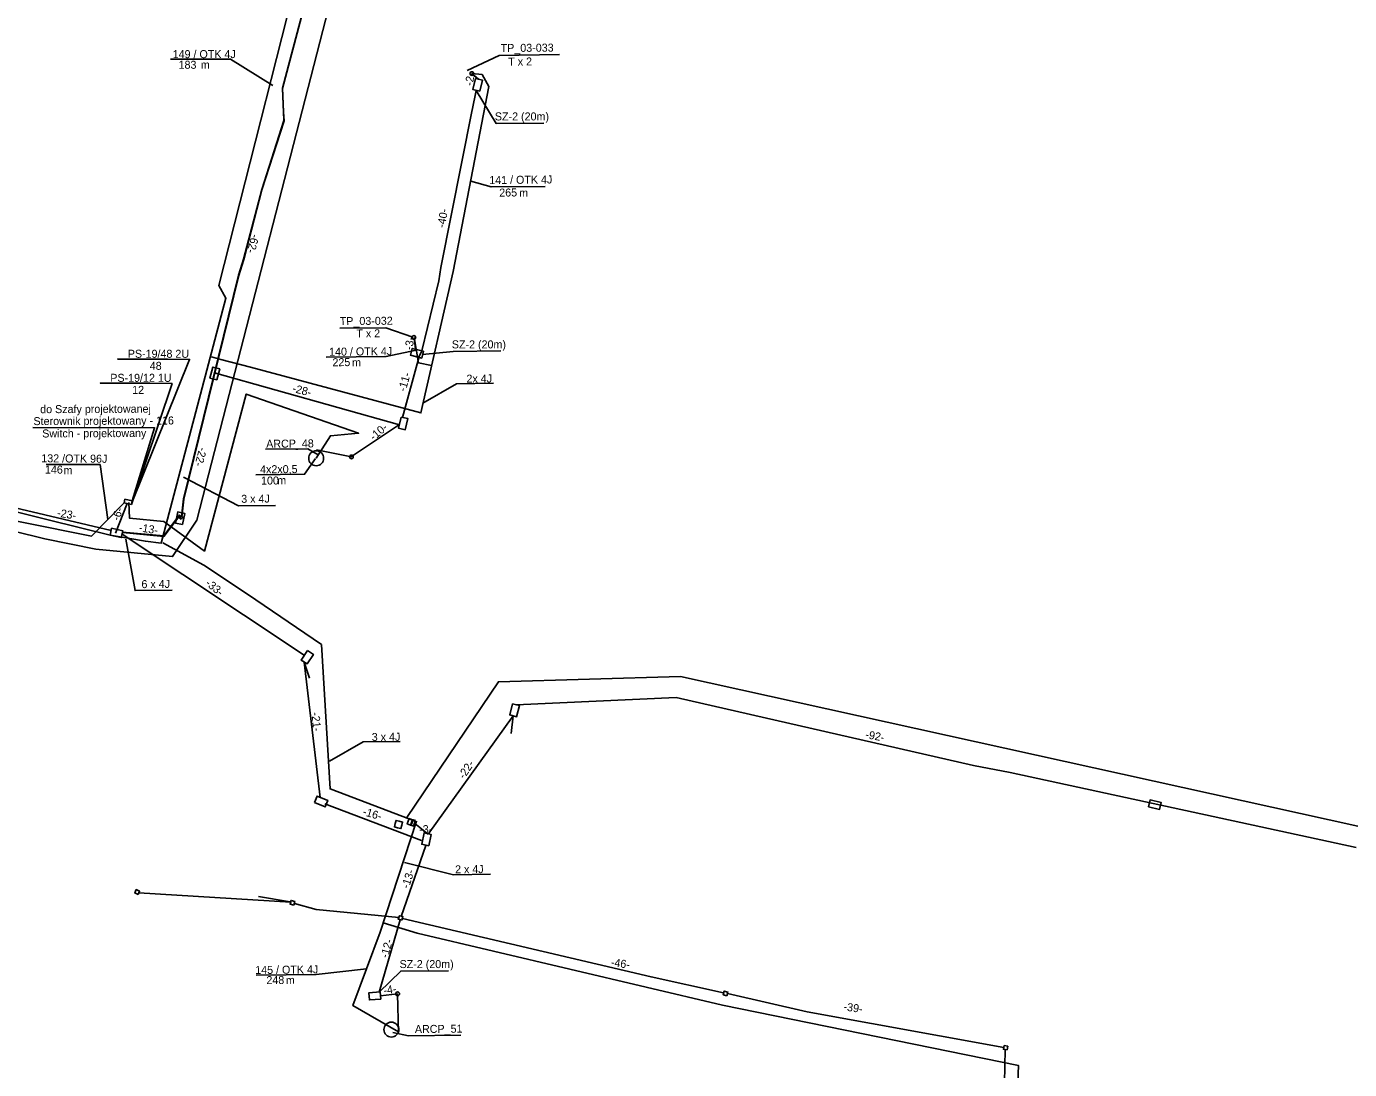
# Model space of a CAD drawing. Extents: x 6494530 to 6506885, y 5884901 to 5892312.
# Drawn here: x 6500530.3 to 6500708, y 5887871.4 to 5888011.5 of the extents above; entities that cross this region are included whole.
import ezdxf

# ---------------------------------------------------------------- set-up
doc = ezdxf.new("R2010")
doc.units = 0
for name, color, linetype in [('kabel do kamery ARCP', 7, 'Continuous'), ('kabel OTK do tab pasaż', 7, 'Continuous'), ('kabel W KANALIZACJI ISTN', 7, 'Continuous'), ('kamery ARCP_nowe', 7, 'Continuous'), ('Kanalizacja_proj', 7, 'Continuous'), ('NOWY OPIS STEROWNIKA', 7, 'Continuous'), ('opis ARCP', 7, 'Continuous'), ('opis kabla CCTV_OTK', 7, 'Continuous'), ('opis kabla infopasażer_OTK', 7, 'Continuous'), ('opis kabla kamery ARCP', 7, 'Continuous'), ('opis kabla otk', 7, 'Continuous'), ('opis PS', 7, 'Continuous'), ('opis SZ-2', 7, 'Continuous'), ('opis tablic inf przystankowej', 7, 'Continuous'), ('proj wysięgnik', 7, 'Continuous'), ('projektowany słup_do_kamery ARCP', 7, 'Continuous'), ('SKR-2', 7, 'Continuous'), ('sterownik', 7, 'Continuous'), ('studnie do wyrysu', 7, 'Continuous'), ('trasa kanalizacji do wyrysu', 7, 'Continuous'), ('Warstwa 59', 7, 'Continuous'), ('Warstwa 62', 7, 'Continuous'), ('WOJEWÓDZKIE', 7, 'Continuous')]:
    doc.layers.add(name, color=color, linetype=linetype)

# ---------------------------------------------------------------- blocks, each defined once
blk = doc.blocks.new('ELARM2_66')
at = {"layer": 'Warstwa 59'}
blk.add_lwpolyline([(0, 0.45), (0.45, 0.45), (0.45, 0), (0.45, -0.45), (0, -0.45), (-0.45, -0.45), (-0.45, 0), (-0.45, 0.45)], close=True, dxfattribs=at)

msp = doc.modelspace()

# ---------------------------------------------------------------- linework, layer by layer
at = {"layer": 'kabel do kamery ARCP'}
msp.add_lwpolyline([(6500569.19, 5887953.51), (6500571.11, 5887956.53), (6500574.89, 5887956.87), (6500559.79, 5887962.13), (6500554.19, 5887941.03), (6500548.73, 5887945.01), (6500544.1, 5887945.46), (6500544.03, 5887947.58)], dxfattribs=at)
at = {"layer": 'kabel OTK do tab pasaż'}
for points in [[(6500576.12, 5888053.57), (6500579.04, 5888052.79), (6500573.17, 5888030.4), (6500568.77, 5888026.66), (6500556.12, 5887976.71), (6500557.07, 5887975.01), (6500548.38, 5887942.11), (6500546.25, 5887942.36), (6500541.51, 5887943.19), (6500533.2, 5887945.22)], [(6500590.1, 5888005.2), (6500591.48, 5888005.06), (6500592.36, 5888003.44), (6500587.61, 5887978.59), (6500583.26, 5887959.61), (6500560.36, 5887965.77), (6500556.37, 5887966.78), (6500555.14, 5887967.14)], [(6500582.33, 5887969.73), (6500582.95, 5887966.35), (6500584.66, 5887965.96)], [(6500461.48, 5887931.47), (6500462.86, 5887930.45), (6500462.92, 5887926.96), (6500481.93, 5887923.99), (6500485.89, 5887929.87), (6500492.78, 5887940.43), (6500500.55, 5887951.93), (6500505.96, 5887955.91), (6500512.86, 5887954.64), (6500524.49, 5887947.38), (6500533.2, 5887945.22)], [(6500548.61, 5887942.15), (6500554.1, 5887939.13), (6500559.98, 5887935.23), (6500569.89, 5887928.48), (6500571.06, 5887909.08), (6500582.73, 5887904.68)], [(6500856.07, 5887892.86), (6500854.23, 5887894.62), (6500834.38, 5887895.31), (6500763.17, 5887887.7), (6500753.04, 5887894.34), (6500618.12, 5887924.18), (6500593.66, 5887923.49), (6500581.36, 5887905.26)], [(6500580.26, 5887876.46), (6500574.12, 5887879.98), (6500577.78, 5887889.83), (6500582.67, 5887904.77)], [(6500578.18, 5887891.11), (6500582.74, 5887889.71), (6500623.78, 5887880.05), (6500663.52, 5887871.9), (6500663.26, 5887865.21), (6500674.63, 5887863.47), (6500676.53, 5887860.66)]]:
    msp.add_lwpolyline(points, dxfattribs=at)
at = {"layer": 'kabel W KANALIZACJI ISTN'}
for points in [[(6500707.09, 5888276.63), (6500683.81, 5888278.53), (6500678.14, 5888274.46), (6500669.69, 5888279.75), (6500661.67, 5888265.1), (6500659.48, 5888263.56), (6500656.02, 5888257.63), (6500645.12, 5888238.44), (6500633.54, 5888219.25), (6500628.37, 5888208), (6500618.89, 5888186.71), (6500611.12, 5888166.91), (6500605.25, 5888152), (6500598.09, 5888143.55), (6500603.16, 5888139.08), (6500596.69, 5888108.65), (6500587.1, 5888068.85), (6500575.46, 5888025.59), (6500572.82, 5888021.64), (6500553.17, 5887945.17)], [(6500543.39, 5887947.52), (6500539.01, 5887943.05), (6500520.48, 5887946.75), (6500511.75, 5887952.5), (6500508.41, 5887953.1), (6500501.97, 5887950.29), (6500454.82, 5887953.91), (6500451.93, 5887943.88), (6500448.56, 5887944.41)], [(6500448.17, 5887943.82), (6500453.23, 5887942.57), (6500456.2, 5887952.23), (6500501.58, 5887948.72), (6500508.52, 5887951.79), (6500511.32, 5887951.28), (6500519.84, 5887945.87), (6500532.73, 5887942.67)], [(6500532.73, 5887942.67), (6500539.59, 5887941.31), (6500549.91, 5887940.29), (6500553.17, 5887945.17)]]:
    msp.add_lwpolyline(points, dxfattribs=at)
at = {"layer": 'kamery ARCP_nowe'}
for centre in [(6500569.19, 5887953.51), (6500579.29, 5887876.75)]:
    msp.add_circle(centre, 1, dxfattribs=at)
at = {"layer": 'Kanalizacja_proj'}
for p, q in [((6500590.96, 5888004.47), (6500590.04, 5888005.18)), ((6500590.1, 5888005.2), (6500590.97, 5888004.45)), ((6500590.14, 5888000.29), (6500590.67, 5888002.93)), ((6500590.15, 5888000.33), (6500585.93, 5887979.12)), ((6500582.33, 5887969.73), (6500582.51, 5887968.15)), ((6500582.33, 5887969.73), (6500582.51, 5887968.15)), ((6500521.88, 5887948.48), (6500541.67, 5887943.82)), ((6500543.81, 5887947.43), (6500542.25, 5887943.46)), ((6500543.12, 5887943.31), (6500567.59, 5887927.04)), ((6500567.59, 5887926.13), (6500568.28, 5887923.97)), ((6500567.59, 5887926.13), (6500569.73, 5887907.94)), ((6500596.03, 5887920.4), (6500617.53, 5887921.36)), ((6500617.53, 5887921.36), (6500657.47, 5887912.21)), ((6500584.24, 5887903.01), (6500595.66, 5887918.91)), ((6500595.66, 5887918.91), (6500595.37, 5887916.55)), ((6500657.47, 5887912.21), (6500662.39, 5887911.27)), ((6500662.39, 5887911.27), (6500708.85, 5887901.21)), ((6500570.34, 5887907.09), (6500583.33, 5887902.15)), ((6500584.25, 5887903.01), (6500582.43, 5887904.42)), ((6500583.91, 5887901.48), (6500580.6, 5887891.95)), ((6500545.37, 5887895.11), (6500565.77, 5887893.86)), ((6500561.44, 5887894.65), (6500565.68, 5887893.9)), ((6500580.49, 5887891.49), (6500577.67, 5887881.78)), ((6500577.83, 5887881.27), (6500580.13, 5887881.55)), ((6500661.52, 5887863.36), (6500661.73, 5887874.05))]:
    msp.add_line(p, q, dxfattribs=at)
for points in [[(6500585.93, 5887979.12), (6500585.66, 5887977.33), (6500583.37, 5887967.95), (6500583, 5887967.16), (6500580.78, 5887958.98)], [(6500555.54, 5887964.98), (6500580.36, 5887958.01)], [(6500573.94, 5887953.76), (6500580.36, 5887958.04)], [(6500566.3, 5887893.71), (6500569.21, 5887892.87), (6500580.28, 5887891.8)], [(6500580.77, 5887891.68), (6500614.16, 5887883.83), (6500623.91, 5887881.67)], [(6500661.54, 5887874.35), (6500635.14, 5887879.14), (6500624.42, 5887881.61)]]:
    msp.add_lwpolyline(points, dxfattribs=at)
for points in [[(6500568.02, 5887927.69), (6500568.81, 5887927.16), (6500567.96, 5887925.87), (6500567.16, 5887926.4)], [(6500568.96, 5887907.24), (6500569.31, 5887908.12), (6500570.74, 5887907.54), (6500570.39, 5887906.66)], [(6500545.27, 5887894.89), (6500544.82, 5887895.1), (6500545.03, 5887895.55), (6500545.48, 5887895.34)], [(6500566.17, 5887893.48), (6500565.69, 5887893.62), (6500565.82, 5887894.1), (6500566.31, 5887893.97)], [(6500580.7, 5887891.44), (6500580.22, 5887891.57), (6500580.36, 5887892.05), (6500580.84, 5887891.92)], [(6500624.35, 5887881.3), (6500623.87, 5887881.43), (6500624, 5887881.92), (6500624.48, 5887881.78)], [(6500661.97, 5887874.01), (6500661.48, 5887874.11), (6500661.59, 5887874.6), (6500662.07, 5887874.5)]]:
    msp.add_lwpolyline(points, close=True, dxfattribs=at)
at = {"layer": 'NOWY OPIS STEROWNIKA'}
msp.add_lwpolyline([(6500544.49, 5887947.77), (6500547.49, 5887957.6), (6500531.15, 5887957.62)], dxfattribs=at)
at = {"layer": 'opis ARCP'}
for points in [[(6500569.46, 5887953.96), (6500568.07, 5887954.79), (6500562.38, 5887954.74)], [(6500588.61, 5887876), (6500581.61, 5887875.92), (6500579.47, 5887876.34)]]:
    msp.add_lwpolyline(points, dxfattribs=at)
at = {"layer": 'opis kabla infopasażer_OTK'}
for points in [[(6500549.63, 5888007.14), (6500557.67, 5888007.12), (6500563.35, 5888003.59)], [(6500589.96, 5887990.76), (6500592.7, 5887989.98), (6500599.93, 5887990.04)], [(6500570.54, 5887967.11), (6500578.57, 5887967.17), (6500582.64, 5887968.04)], [(6500561.15, 5887884.06), (6500569.19, 5887884.13), (6500575.95, 5887884.9)]]:
    msp.add_lwpolyline(points, dxfattribs=at)
at = {"layer": 'opis kabla kamery ARCP'}
msp.add_lwpolyline([(6500561.09, 5887951.27), (6500567.64, 5887951.35), (6500569.11, 5887953.47)], dxfattribs=at)
at = {"layer": 'opis kabla otk'}
for points in [[(6500583.5, 5887960.93), (6500588.05, 5887963.53), (6500593.01, 5887963.58)], [(6500532.93, 5887952.68), (6500540.16, 5887952.65), (6500541.2, 5887945.29)], [(6500551.38, 5887950.95), (6500558.78, 5887947.12), (6500563.74, 5887947.16)], [(6500543.64, 5887942.66), (6500544.86, 5887935.73), (6500549.83, 5887935.77)], [(6500570.96, 5887912.79), (6500575.5, 5887915.39), (6500580.47, 5887915.44)], [(6500581.04, 5887899.19), (6500587.65, 5887897.56), (6500592.62, 5887897.61)]]:
    msp.add_lwpolyline(points, dxfattribs=at)
at = {"layer": 'opis PS'}
for points in [[(6500549.22, 5887966.81), (6500542.54, 5887966.84), (6500542.54, 5887966.84), (6500542.54, 5887966.84), (6500552.19, 5887966.78), (6500544.43, 5887947.53)], [(6500546.87, 5887963.59), (6500540.19, 5887963.62), (6500540.19, 5887963.62), (6500540.19, 5887963.62), (6500549.83, 5887963.55), (6500544.37, 5887947.29)]]:
    msp.add_lwpolyline(points, dxfattribs=at)
at = {"layer": 'opis SZ-2'}
for points in [[(6500590.69, 5888002.92), (6500593.35, 5887998.5), (6500599.77, 5887998.55)], [(6500583.48, 5887967.43), (6500587.58, 5887967.87), (6500593.99, 5887967.92)], [(6500577.67, 5887881.78), (6500580.55, 5887884.61), (6500586.97, 5887884.66)]]:
    msp.add_lwpolyline(points, dxfattribs=at)
at = {"layer": 'opis tablic inf przystankowej'}
for points in [[(6500601.87, 5888007.74), (6500593.75, 5888007.64), (6500589.46, 5888005.61)], [(6500572.38, 5887970.97), (6500578.53, 5887971.02), (6500582.17, 5887969.76)]]:
    msp.add_lwpolyline(points, dxfattribs=at)
at = {"layer": 'proj wysięgnik'}
for p, q in [((6500573.93, 5887953.69), (6500569.22, 5887954.66)), ((6500580.13, 5887881.55), (6500580.25, 5887876.35))]:
    msp.add_line(p, q, dxfattribs=at)
at = {"layer": 'projektowany słup_do_kamery ARCP'}
for centre in [(6500573.93, 5887953.69), (6500580.13, 5887881.55)]:
    msp.add_circle(centre, 0.25, dxfattribs=at)
at = {"layer": 'SKR-2'}
for points in [[(6500591.15, 5888002.81), (6500590.23, 5888003.04), (6500590.6, 5888004.53), (6500591.53, 5888004.3)], [(6500583.6, 5887967.9), (6500583.37, 5887966.97), (6500581.87, 5887967.35), (6500582.1, 5887968.27)], [(6500555.85, 5887964.03), (6500554.92, 5887964.27), (6500555.33, 5887965.76), (6500556.25, 5887965.51)], [(6500580.6, 5887959.05), (6500581.52, 5887958.83), (6500581.16, 5887957.33), (6500580.23, 5887957.56)], [(6500551.23, 5887944.59), (6500550.3, 5887944.78), (6500550.6, 5887946.29), (6500551.54, 5887946.1)], [(6500541.51, 5887943.19), (6500541.72, 5887944.11), (6500543.22, 5887943.77), (6500543.01, 5887942.84)], [(6500595.57, 5887920.52), (6500596.49, 5887920.29), (6500596.11, 5887918.79), (6500595.19, 5887919.03)], [(6500680.96, 5887906.68), (6500681.18, 5887907.61), (6500682.68, 5887907.25), (6500682.46, 5887906.32)], [(6500680.96, 5887906.68), (6500681.18, 5887907.61), (6500682.68, 5887907.25), (6500682.46, 5887906.32)], [(6500583.69, 5887903.16), (6500584.62, 5887902.96), (6500584.31, 5887901.45), (6500583.37, 5887901.65)], [(6500577.79, 5887881.8), (6500577.87, 5887880.85), (6500576.33, 5887880.73), (6500576.26, 5887881.68)]]:
    msp.add_lwpolyline(points, close=True, dxfattribs=at)
at = {"layer": 'sterownik'}
msp.add_lwpolyline([(6500544.37, 5887947.29), (6500543.39, 5887947.52), (6500543.5, 5887948), (6500544.49, 5887947.77)], close=True, dxfattribs=at)
at = {"layer": 'studnie do wyrysu'}
msp.add_lwpolyline([(6500551.05, 5887945.31), (6500551.27, 5887945.59), (6500551.07, 5887945.74), (6500550.85, 5887945.47)], close=True, dxfattribs=at)
msp.add_lwpolyline([(6500551.05, 5887945.31), (6500551.27, 5887945.59), (6500551.07, 5887945.74), (6500550.85, 5887945.47)], close=True, dxfattribs=at)
msp.add_lwpolyline([(6500551.05, 5887945.31), (6500551.27, 5887945.59), (6500551.07, 5887945.74), (6500550.85, 5887945.47)], close=True, dxfattribs=at)
msp.add_lwpolyline([(6500551.05, 5887945.31), (6500551.27, 5887945.59), (6500551.07, 5887945.74), (6500550.85, 5887945.47)], close=True, dxfattribs=at)
at = {"layer": 'trasa kanalizacji do wyrysu'}
for points in [[(6500587.06, 5888082), (6500585.84, 5888076.11), (6500584.31, 5888071.63), (6500581.39, 5888065.83), (6500578.3, 5888055.51), (6500575.09, 5888048.81), (6500572.49, 5888038.86), (6500571.52, 5888034.7), (6500571.84, 5888031.86), (6500569.96, 5888023.79), (6500568.42, 5888017.47), (6500564.65, 5888003.22), (6500564.79, 5888000.05)], [(6500587.06, 5888082), (6500585.84, 5888076.11), (6500584.31, 5888071.63), (6500581.39, 5888065.83), (6500578.3, 5888055.51), (6500575.09, 5888048.81), (6500572.49, 5888038.86), (6500571.52, 5888034.7), (6500571.84, 5888031.86), (6500569.96, 5888023.79), (6500568.42, 5888017.47), (6500564.65, 5888003.22), (6500564.79, 5888000.05)], [(6500587.08, 5888081.94), (6500585.86, 5888076.06), (6500584.33, 5888071.58), (6500581.41, 5888065.78), (6500578.32, 5888055.46), (6500575.11, 5888048.76), (6500572.51, 5888038.81), (6500571.54, 5888034.65), (6500571.86, 5888031.81), (6500569.98, 5888023.74), (6500568.44, 5888017.42), (6500564.67, 5888003.17), (6500564.82, 5888000)], [(6500587.08, 5888081.94), (6500585.86, 5888076.06), (6500584.33, 5888071.58), (6500581.41, 5888065.78), (6500578.32, 5888055.46), (6500575.11, 5888048.76), (6500572.51, 5888038.81), (6500571.54, 5888034.65), (6500571.86, 5888031.81), (6500569.98, 5888023.74), (6500568.44, 5888017.42), (6500564.67, 5888003.17), (6500564.82, 5888000)], [(6500587.08, 5888081.94), (6500585.86, 5888076.06), (6500584.33, 5888071.58), (6500581.41, 5888065.78), (6500578.32, 5888055.46), (6500575.11, 5888048.76), (6500572.51, 5888038.81), (6500571.54, 5888034.65), (6500571.86, 5888031.81), (6500569.98, 5888023.74), (6500568.44, 5888017.42), (6500564.67, 5888003.17), (6500564.82, 5888000)], [(6500587.08, 5888081.94), (6500585.86, 5888076.06), (6500584.33, 5888071.58), (6500581.41, 5888065.78), (6500578.32, 5888055.46), (6500575.11, 5888048.76), (6500572.51, 5888038.81), (6500571.54, 5888034.65), (6500571.86, 5888031.81), (6500569.98, 5888023.74), (6500568.44, 5888017.42), (6500564.67, 5888003.17), (6500564.82, 5888000)], [(6500564.79, 5888000.05), (6500564.85, 5887998.89), (6500561.87, 5887989.61), (6500559.44, 5887980.27), (6500558.78, 5887978.11), (6500551.38, 5887948.06), (6500551.11, 5887945.63)], [(6500564.79, 5888000.05), (6500564.85, 5887998.89), (6500561.87, 5887989.61), (6500559.44, 5887980.27), (6500558.78, 5887978.11), (6500551.38, 5887948.06), (6500551.11, 5887945.63)], [(6500564.82, 5888000), (6500564.87, 5887998.84), (6500561.89, 5887989.56), (6500559.46, 5887980.22), (6500558.8, 5887978.06), (6500551.4, 5887948.01), (6500551.13, 5887945.58)], [(6500564.82, 5888000), (6500564.87, 5887998.84), (6500561.89, 5887989.56), (6500559.46, 5887980.22), (6500558.8, 5887978.06), (6500551.4, 5887948.01), (6500551.13, 5887945.58)], [(6500564.82, 5888000), (6500564.87, 5887998.84), (6500561.89, 5887989.56), (6500559.46, 5887980.22), (6500558.8, 5887978.06), (6500551.4, 5887948.01), (6500551.13, 5887945.58)], [(6500564.82, 5888000), (6500564.87, 5887998.84), (6500561.89, 5887989.56), (6500559.46, 5887980.22), (6500558.8, 5887978.06), (6500551.4, 5887948.01), (6500551.13, 5887945.58)], [(6500551, 5887945.74), (6500550.85, 5887945.9), (6500548.71, 5887943.07), (6500548.71, 5887943.07), (6500543.2, 5887943.58)], [(6500551, 5887945.74), (6500550.85, 5887945.9), (6500548.71, 5887943.07), (6500548.71, 5887943.07), (6500543.2, 5887943.58)], [(6500551.02, 5887945.69), (6500550.88, 5887945.84), (6500548.74, 5887943.01), (6500548.74, 5887943.01), (6500543.23, 5887943.52)], [(6500551.02, 5887945.69), (6500550.88, 5887945.84), (6500548.74, 5887943.01), (6500548.74, 5887943.01), (6500543.23, 5887943.52)], [(6500551.02, 5887945.69), (6500550.88, 5887945.84), (6500548.74, 5887943.01), (6500548.74, 5887943.01), (6500543.23, 5887943.52)], [(6500551.02, 5887945.69), (6500550.88, 5887945.84), (6500548.74, 5887943.01), (6500548.74, 5887943.01), (6500543.23, 5887943.52)]]:
    msp.add_lwpolyline(points, dxfattribs=at)
at = {"layer": 'Warstwa 59'}
for points in [[(6500551.05, 5887945.31), (6500551.27, 5887945.59), (6500551.07, 5887945.74), (6500550.85, 5887945.47)], [(6500581.7, 5887905.11), (6500581.42, 5887904.37), (6500581.84, 5887904.21), (6500582.12, 5887904.95)], [(6500582.53, 5887904.83), (6500582.25, 5887904.1), (6500581.94, 5887904.22), (6500582.22, 5887904.95)]]:
    msp.add_lwpolyline(points, close=True, dxfattribs=at)
at = {"layer": 'Warstwa 62'}
for centre in [(6500590.09, 5888005.19), (6500582.32, 5887969.74)]:
    msp.add_circle(centre, 0.25, dxfattribs=at)

# ---------------------------------------------------------------- block references
at = {"layer": 'Warstwa 59', "xscale": 1.0000018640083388, "yscale": 1.0000018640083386, "rotation": -14.253020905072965}
msp.add_blockref('ELARM2_66', (6500580.24, 5887904.31), dxfattribs=at)

# ---------------------------------------------------------------- texts
at = {"layer": 'NOWY OPIS STEROWNIKA'}
for s, p in [(' do Szafy projektowanej', (6500531.73, 5887959.56)), ('Sterownik projektowany - 116', (6500531.23, 5887957.96)), ('Switch - projektowany', (6500532.4, 5887956.3))]:
    msp.add_text(s, height=1.075, rotation=0.2709, dxfattribs=at).set_placement(p)
at = {"layer": 'opis ARCP'}
for s, rotation, p in [('ARCP_48', 0.5591, (6500562.48, 5887954.91)), ('ARCP_51', 0.4877, (6500582.45, 5887876.28))]:
    msp.add_text(s, height=1.075, rotation=rotation, dxfattribs=at).set_placement(p)
at = {"layer": 'opis kabla CCTV_OTK'}
for s, height, p in [('132 /OTK 96J', 1.075, (6500532.27, 5887952.97)), ('146', 1.075, (6500532.76, 5887951.46)), ('m', 1.07, (6500535.26, 5887951.37))]:
    msp.add_text(s, height=height, rotation=359.5649, dxfattribs=at).set_placement(p)
at = {"layer": 'opis kabla infopasażer_OTK'}
for s, height, p in [('149 / OTK 4J', 1.075, (6500549.92, 5888007.27)), ('183', 1.075, (6500550.71, 5888005.84)), ('m', 1.07, (6500553.7, 5888005.85))]:
    msp.add_text(s, height=height, dxfattribs=at).set_placement(p)
for s, height, rotation, p in [('141 / OTK 4J', 1.075, 0.6422, (6500592.44, 5887990.34)), ('265', 1.075, 0.6422, (6500593.78, 5887988.66)), ('m', 1.07, 0.6422, (6500596.46, 5887988.64)), ('140 / OTK 4J', 1.075, 0.5807, (6500570.93, 5887967.28)), ('225', 1.075, 0.5807, (6500571.38, 5887965.87)), ('m', 1.08, 0.5807, (6500574.01, 5887965.84)), ('145 / OTK 4J', 1.075, 0.6398, (6500561.01, 5887884.21)), ('248', 1.075, 0.6398, (6500562.51, 5887882.85)), ('m', 1.08, 0.6398, (6500565.12, 5887882.85))]:
    msp.add_text(s, height=height, rotation=rotation, dxfattribs=at).set_placement(p)
at = {"layer": 'opis kabla kamery ARCP'}
for s, height, p in [('4x2x0,5', 1.075, (6500561.66, 5887951.49)), ('100', 1.075, (6500561.79, 5887949.97)), ('m', 1.08, (6500563.96, 5887950))]:
    msp.add_text(s, height=height, rotation=0.3645, dxfattribs=at).set_placement(p)
at = {"layer": 'opis kabla otk'}
for s, p in [('2x 4J', (6500589.38, 5887963.66)), ('3 x 4J', (6500559.13, 5887947.52)), ('6 x 4J', (6500545.73, 5887936.06)), ('3 x 4J', (6500576.66, 5887915.52)), ('2 x 4J', (6500587.85, 5887897.74))]:
    msp.add_text(s, height=1.075, rotation=0.5229, dxfattribs=at).set_placement(p)
at = {"layer": 'opis PS'}
for s, p in [('PS-19/48 2U', (6500543.89, 5887967.01)), ('PS-19/12 1U', (6500541.54, 5887963.78)), ('48', (6500546.84, 5887965.39)), ('12', (6500544.48, 5887962.16))]:
    msp.add_text(s, height=1.075, dxfattribs=at).set_placement(p)
at = {"layer": 'opis SZ-2'}
for p in [(6500593.19, 5887998.9), (6500587.41, 5887968.27), (6500580.39, 5887885.01)]:
    msp.add_text('SZ-2 (20m)', height=1.075, dxfattribs=at).set_placement(p)
at = {"layer": 'opis tablic inf przystankowej'}
for s, rotation, p in [('TP_03-033', 0.4397, (6500593.97, 5888008.09)), ('T x 2', 0.4397, (6500594.99, 5888006.26)), ('TP_03-032', 0.527, (6500572.36, 5887971.39)), ('T x 2', 0.527, (6500574.59, 5887969.73))]:
    msp.add_text(s, height=1.075, rotation=rotation, dxfattribs=at).set_placement(p)
at = {"layer": 'trasa kanalizacji do wyrysu'}
for s, p in [('-62-', (6500560.53, 5887983.69)), ('-22-', (6500553.5, 5887955.05))]:
    msp.add_text(s, height=1.075, rotation=255.5523, dxfattribs=at).set_placement(p)
at = {"layer": 'WOJEWÓDZKIE'}
for s, rotation, p in [('-2-', 80.2728, (6500590.2, 5888003.5)), ('-40-', 80.2728, (6500586.47, 5887984.41)), ('-3-', 80.2728, (6500582.1, 5887968)), ('-11-', 74.1928, (6500581.2, 5887962.4)), ('-28-', 345.6672, (6500565.91, 5887962.44)), ('-10-', 40.3533, (6500576.93, 5887955.83)), ('-23-', 350.7694, (6500534.34, 5887945.68)), ('-6-', 69.8622, (6500542.7, 5887945.02)), ('-13-', 350.7694, (6500545.32, 5887943.7)), ('-33-', 320.5279, (6500554.23, 5887936.55)), ('-21-', 274.8767, (6500568.57, 5887919.34)), ('-92-', 349.6535, (6500642.88, 5887915.91)), ('-22-', 56.4252, (6500589.07, 5887910.34)), ('-16-', 343.4991, (6500575.36, 5887905.59)), ('-3-', 1.7937, (6500583.04, 5887903.11)), ('-13-', 71.758, (6500581.61, 5887895.61)), ('-12-', 74.4248, (6500578.81, 5887886.28)), ('-46-', 351.5494, (6500608.71, 5887885.3)), ('-4-', 8.5804, (6500578.3, 5887881.46)), ('-39-', 351.5494, (6500639.96, 5887879.34))]:
    msp.add_text(s, height=1.075, rotation=rotation, dxfattribs=at).set_placement(p)

doc.saveas('drawing.dxf')
